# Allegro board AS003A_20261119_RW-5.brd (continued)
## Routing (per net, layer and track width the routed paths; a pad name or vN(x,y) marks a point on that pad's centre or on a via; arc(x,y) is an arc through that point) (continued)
D12705: length 380.6
  L30_DIG w0.081: D127.05 24.12,57.14 24.12,116.27 30.59,122.74 88.68,122.74 100.01,134.07 100.01,152.73 176.13,228.85 219.88,228.85 220.74,229.71 223.68,229.71 224.53,228.85 226.75,228.85 231.7,223.9 264.39,223.9 264.77,223.52 266.83,223.52 269.25,221.11 269.9,221.11 272.28,218.73 272.28,218.02 273.04,217.27 275.63,217.27 275.87,217.03 277.75,217.03
  L30_DIG w0.102: v1(280.03,216.63) 279.63,217.03 277.75,217.03
D12706: length 365.7
  L09_DIG w0.081: 277.75,218.63 276.18,218.63 275.23,219.58 267.26,219.58 262.65,224.18 226.57,224.18 225.45,225.31 152.57,225.31 81.84,154.58 81.84,137.08 73.78,129.02 50.71,129.02 26.67,104.99 26.67,59.86 25.41,58.6
  L09_DIG w0.102: v1(282.43,218.23) 282.03,218.63 277.75,218.63
D12707: length 369.9
  L30_DIG w0.081: D127.07 29.44,57.38 29.44,112.84 34.28,117.68 90.49,117.68 109.52,136.71 109.52,154.42 180.48,225.38 224.99,225.38 228.57,221.8 250.52,221.8 251.24,221.07 266.47,221.07 270.59,216.95 270.59,216.19 271.35,215.43 277.75,215.43
  L30_DIG w0.102: 277.75,215.43 279.63,215.43 v1(280.03,215.03)
D12708: length 353
  L09_DIG w0.081: 277.75,215.43 273.93,215.43 271.87,217.49 261.71,217.49 259.12,220.08 250.03,220.08 249.28,220.83 163.9,220.83 88.76,145.69 88.76,137.54 76.43,125.21 51.83,125.21 31.62,104.99 31.62,59.53 30.53,58.44
  L09_DIG w0.102: v1(282.43,215.03) 282.03,215.43 277.75,215.43
D12709: length 362.2
  L30_DIG w0.081: D127.09 34.18,57.04 34.18,107.53 38.88,112.23 95.08,112.23 119.89,137.03 119.89,159.67 181.06,220.85 224.59,220.85 227.18,218.25 255.15,218.25 256.29,219.39 259.07,219.39 259.38,219.08 265,219.08 270.24,213.83 277.75,213.83
  L30_DIG w0.102: 277.75,213.83 279.63,213.83 v1(280.03,213.43)
D12710: length 344.9
  L09_DIG w0.081: 35.59,58.33 36.82,59.56 36.82,104.04 53.88,121.1 77.63,121.1 93.41,136.88 93.41,145.52 164.15,216.26 250.03,216.26 252.35,213.94 270.29,213.94 270.58,213.65 275.48,213.65 276.1,213.03 277.75,213.03
  L09_DIG w0.102: v1(282.43,212.63) 282.03,213.03 277.75,213.03
D12711: length 383.2
  L32_DIG w0.081: D127.11 39.32,57.1 39.32,118.14 57.8,136.61 113.15,136.61 124.74,148.2 124.74,208.06 138.17,221.49 162.58,221.49 165.65,218.42 247.93,218.42 250.92,215.43 277.75,215.43
  L32_DIG w0.102: v1(279.23,215.03) 278.83,215.43 277.75,215.43
D12712: length 335.2
  L09_DIG w0.081: 40.63,58.09 42.13,59.59 42.13,103.29 56.04,117.2 78.7,117.2 98.62,137.12 98.62,146.34 160.89,208.61 219.85,208.61 220.58,209.34 223.92,209.34 226.43,211.85 275.58,211.85 275.99,211.43 277.75,211.43
  L09_DIG w0.102: v1(280.83,211.03) 280.43,211.43 277.75,211.43
D12713: length 366.5
  L32_DIG w0.081: 277.75,213.03 276.27,213.03 275.52,212.28 225.38,212.28 224.24,213.43 183.57,213.43 180.61,210.46 148.09,210.46 131.86,194.24 131.86,142.97 120.28,131.38 60.28,131.38 44.26,115.36 44.26,56.96 D127.13
  L32_DIG w0.102: v1(279.23,212.63) 278.83,213.03 277.75,213.03
D12714: length 329.1
  L09_DIG w0.081: 277.75,209.83 276.95,209.83 276.07,208.95 267.01,208.95 264.8,206.73 225.8,206.73 223.94,204.87 162.43,204.87 103.92,146.36 103.92,137.3 78.32,111.69 55,111.69 47.06,103.75 47.06,59.76 D127.14
  L09_DIG w0.102: v1(280.83,209.43) 280.43,209.83 277.75,209.83
D12715: length 359
  L32_DIG w0.081: 277.75,209.83 276.39,209.83 275.28,208.72 267.3,208.72 265.34,206.76 149.33,206.76 136.09,193.52 136.09,140.62 121.64,126.17 62.05,126.17 49.61,113.73 49.61,57.23 D127.15
  L32_DIG w0.102: v1(279.23,209.43) 278.83,209.83 277.75,209.83
D12716: length 309.5
  L09_DIG w0.081: D127.16 55.51,63.13 55.51,82.93 107.04,134.47 107.04,144.19 163.51,200.65 250.83,200.65 252.39,202.2 264.59,202.2 269.32,206.93 276.08,206.93 277.38,208.23 277.75,208.23
  L09_DIG w0.102: v1(280.83,207.83) 280.43,208.23 277.75,208.23
D12801: length 473.7
  L32_DIG w0.081: 277.75,223.43 276.62,223.43 275.49,224.56 273.34,224.56 271.44,226.47 256.23,226.47 252.35,230.36 230.99,230.36 227.1,234.24 220.61,234.24 219.86,233.49 10.94,233.49 8.74,231.29 8.74,39.52 D128.01
  L32_DIG w0.102: 277.75,223.43 278.83,223.43 v1(279.23,223.03)
D12802: length 414.8
  L30_DIG w0.081: D128.02 16.57,39.43 16.57,115.5 29.39,128.32 77.07,128.32 85.82,137.07 85.82,160.01 162.63,236.82 226.49,236.82 234.91,228.39 269.41,228.39 272.06,225.74 272.06,224.15 273.99,222.22 273.99,220.16 274.52,219.64 275.81,219.64 276.4,220.23 277.75,220.23
  L30_DIG w0.102: v1(280.03,219.83) 279.63,220.23 277.75,220.23
D12803: length 433.8
  L32_DIG w0.081: D128.03 19.01,36.79 19.01,122.11 44.44,147.54 100.2,147.54 111.04,158.38 111.04,215.71 125.83,230.51 220,230.51 220.6,229.91 223.66,229.91 224.19,230.44 225.37,230.44 228.23,227.58 250.08,227.58 254.82,222.84 266.65,222.84 268.5,220.98 275.3,220.98 276.05,220.23 277.75,220.23
  L32_DIG w0.102: v1(282.43,219.83) 282.03,220.23 277.75,220.23
D12804: length 402.4
  L30_DIG w0.081: D128.04 21.42,39.2 21.42,116.74 30.08,125.4 84.75,125.4 95.87,136.52 95.87,152.77 175.37,232.28 225.57,232.28 231.58,226.27 249.63,226.27 250.68,225.22 267.09,225.22 271.16,221.15 271.79,221.15 272.61,220.33 272.61,218.27 273.05,217.83 277.75,217.83
  L30_DIG w0.102: v1(280.03,217.43) 279.63,217.83 277.75,217.83
D12805: length 423.6
  L32_DIG w0.081: D128.05 24.12,36.82 24.12,123.35 46.24,145.48 102.96,145.48 114.01,156.52 114.01,213.65 127.95,227.59 224.28,227.59 225.4,226.47 249.33,226.47 254.51,221.29 265.72,221.29 267.58,219.43 277.75,219.43
  L32_DIG w0.102: 277.75,219.43 278.83,219.43 v1(279.23,219.03)
D12806: length 394.9
  L30_DIG w0.081: 277.75,216.23 276.95,216.23 276.71,215.99 271.54,215.99 271.07,216.45 271.07,218.2 266.29,222.98 229.42,222.98 224.79,227.62 177.94,227.62 105.17,154.85 105.17,135.33 90.04,120.2 31.96,120.2 26.85,115.09 26.85,39.55 D128.06
  L30_DIG w0.102: 277.75,216.23 279.63,216.23 v1(280.03,215.83)
D12807: length 415.2
  L32_DIG w0.081: D128.07 29.23,36.85 29.23,118.17 53.3,142.24 105.38,142.24 117.24,154.1 117.24,211.5 132.04,226.29 165.92,226.29 169.22,222.99 249.6,222.99 252.09,220.5 261.12,220.5 263.79,217.83 277.75,217.83
  L32_DIG w0.102: 277.75,217.83 278.83,217.83 v1(279.23,217.43)
D12808: length 385
  L30_DIG w0.081: 277.75,214.63 276.31,214.63 276,214.32 271.34,214.32 267.28,218.38 267.28,218.87 265.88,220.27 250.55,220.27 250.16,220.66 226.81,220.66 224.41,223.06 180.46,223.06 115.28,157.89 115.28,134.85 95.29,114.85 36.94,114.85 31.82,109.74 31.82,39.44 D128.08
  L30_DIG w0.102: 277.75,214.63 279.63,214.63 v1(280.03,214.23)
D12809: length 413.8
  L32_DIG w0.081: D128.09 34.28,36.82 34.28,117.68 56.25,139.65 111.2,139.65 121.83,150.28 121.83,210.62 135.19,223.98 165.12,223.98 167.98,221.12 248.73,221.12 252.45,217.4 262.44,217.4 263.89,215.95 276.38,215.95 276.66,216.23 277.75,216.23
  L32_DIG w0.102: 277.75,216.23 282.03,216.23 v1(282.43,215.83)
D12810: length 376
  L30_DIG w0.081: 277.75,213.03 276.16,213.03 275.56,212.43 269.77,212.43 264.89,217.32 225.05,217.32 224.11,218.25 181.16,218.25 124.77,161.86 124.77,135.14 100.01,110.39 42.22,110.39 36.84,105 36.84,39.38 D128.10
  L30_DIG w0.102: 277.75,213.03 279.63,213.03 v1(280.03,212.63)
D12811: length 473.7
  L30_DIG w0.081: 277.75,221.83 276.62,221.83 275.7,222.75 275.7,224.03 273.56,226.17 273.56,227.58 270.47,230.68 267.4,230.68 265.59,232.49 238.92,232.49 238.71,232.7 238.71,233 238.92,233.21 249.51,233.21 249.7,233.4 249.7,233.69 249.47,233.92 234.85,233.92 227.44,241.33 161.88,241.33 81.59,161.04 81.59,149.87 65.7,133.98 28.27,133.98 11.01,116.72 11.01,32.44 13.13,30.33 32.87,30.33 D128.11
  L30_DIG w0.102: 277.75,221.83 279.63,221.83 v1(280.03,221.43)
D12812: length 395.1
  L32_DIG w0.081: D128.12 42.01,39.47 42.01,117.53 58.51,134.02 115.57,134.02 129.55,148 129.55,202.74 146.86,220.06 160.63,220.06 164.66,216.04 248.68,216.04 251.27,213.44 260.85,213.44 261.45,214.04 275.49,214.04 276.08,214.63 277.75,214.63
  L32_DIG w0.102: 277.75,214.63 278.83,214.63 v1(279.23,214.23)
D12813: length 473.7
  L30_DIG w0.081: D128.13 34.67,27.05 11.9,27.05 8.83,30.11 8.83,118.67 27.17,137.01 64.39,137.01 79.39,152.01 79.39,162.98 160.03,243.63 227.66,243.63 229.91,241.38 271.84,241.38 276.4,236.82 276.4,223.58 277.35,222.63 277.75,222.63
  L30_DIG w0.102: 277.75,222.63 279.63,222.63 v1(280.03,223.03)
D12814: length 380.9
  L32_DIG w0.081: D128.14 46.9,39.28 46.9,114.47 61.83,129.4 121.62,129.4 133.76,141.53 133.76,193.69 148.07,208 181.27,208 184.71,211.44 224.87,211.44 225.93,210.39 275.74,210.39 276.79,211.43 277.75,211.43
  L32_DIG w0.102: v1(279.23,211.03) 278.83,211.43 277.75,211.43
D12815: length 456.5
  L07_DIG w0.081: D128.15 62.85,20.97 269.27,20.97 290.03,41.74 313.91,41.74 316.37,44.2 316.37,121.01 300.08,137.3 300.08,164.09 300.9,164.92 300.9,170.65 300.03,171.53 300.03,175.28 301.04,176.3 301.04,189.11 296.79,193.36 296.79,199.92 296.43,200.27 296.43,201.55
  L07_DIG w0.102: 296.43,201.55 296.43,205.73 296.33,205.83 295.63,205.83 v1(295.23,206.23)
D12816: length 327.7
  L09_DIG w0.081: 277.75,206.63 277.11,206.63 275.58,205.1 269.22,205.1 261.55,197.43 226.28,197.43 224.49,195.64 161.01,195.64 109.32,143.95 109.32,132.36 58.39,81.43 58.39,45.69 D128.16
  L09_DIG w0.102: 277.75,206.63 280.43,206.63 v1(280.83,206.23)
D12901: length 433.8
  L07_DIG w0.081: D129.01 84.56,94.72 84.56,45.19 80.77,41.39 67.61,41.39 63.22,45.78 63.22,60.16 69,65.95 77.85,65.95 79.16,67.26 79.16,148.81 139.42,209.07 151.88,209.07 174.91,232.1 224.24,232.1 227.88,228.46 249.89,228.46 251.96,226.38 267.51,226.38 268.92,224.97 268.92,223.59 269.71,222.81 275.71,222.81 276.68,221.83 277.75,221.83
  L07_DIG w0.102: 277.75,221.83 281.23,221.83 v1(281.63,221.43)
D12902: length 314.6
  L03_DIG w0.096: 277.75,208.63 277.67,208.63 277.59,208.63 277.57,208.61 277.3,208.6 276.19,208.6 275.92,208.87 269.95,208.87 266.58,212.25 229.34,212.25 227.57,214.02 177.03,214.02 84.47,121.46 84.47,109.58 76.29,101.4 76.29,84.1 78.49,81.9 83.55,81.9 85.04,83.39 85.04,100.85 87.01,102.83 90.33,102.83 91.25,101.91 91.25,100.82 90.68,100.25 90.09,100.25 D129.02
  L03_DIG w0.102: 277.75,208.63 v1(278.43,208.63)
D12903: length 279.8
  L07_DIG w0.081: 277.75,219.43 271.67,219.43 270.05,221.05 269.49,221.05 267.87,222.67 267.87,224.27 266.68,225.46 251.52,225.46 249.73,227.25 226.36,227.25 223.78,229.83 220.74,229.83 219.72,228.81 174.24,228.81 94.33,148.9 94.33,107.36 92.41,105.44 92.41,97.49 D129.03
  L07_DIG w0.102: v1(281.63,219.03) 281.23,219.43 277.75,219.43
D12904: length 314.6
  L03_DIG w0.096: D129.04 91.62,101.42 91.62,102.06 90.48,103.2 86.86,103.2 84.67,101.01 84.67,83.54 83.4,82.27 78.64,82.27 76.66,84.25 76.66,101.25 84.83,109.42 84.83,121.3 177.19,213.65 227.41,213.65 229.19,211.88 266.42,211.88 269.8,208.51 275.76,208.51 276.03,208.24 277.31,208.24 277.58,208.24 277.6,208.23 277.68,208.23 277.75,208.23
  L03_DIG w0.102: 277.75,208.23 278.83,208.23 v1(279.23,208.63)
D12905: length 275.6
  L07_DIG w0.081: 277.75,217.83 271.42,217.83 266.28,222.97 252.47,222.97 249.22,226.23 225.9,226.23 224.58,227.54 175.48,227.54 100.48,152.54 100.48,111.04 97.83,108.38 97.83,97.83 D129.05
  L07_DIG w0.102: 277.75,217.83 281.93,217.83 282.03,217.93 282.03,218.63 v1(282.43,219.03)
D12906: length 314.6
  L03_DIG w0.096: D129.06 100.41,100.41 100.41,103.2 98.81,104.8 86.18,104.8 83.6,102.22 83.6,87.31 82.39,86.11 79.33,86.11 77.92,87.52 77.92,100.88 86.11,109.07 86.11,120.76 177.12,211.77 226.1,211.77 227.57,210.3 265,210.3 268.24,207.06 275.82,207.06 276.17,207.41 277.59,207.41 277.61,207.43 277.75,207.43
  L03_DIG w0.102: v1(279.23,207.03) 278.83,207.43 277.75,207.43
D12907: length 269
  L07_DIG w0.081: 277.75,216.23 276.54,216.23 275.38,217.39 270.11,217.39 266.44,221.06 251.99,221.06 249.15,223.9 226.48,223.9 225.12,225.27 176.15,225.27 105.87,154.98 105.87,108.63 102.83,105.59 102.83,97.75 D129.07
  L07_DIG w0.102: 277.75,216.23 281.23,216.23 v1(281.63,215.83)
D12908: length 314.6
  L03_DIG w0.096: D129.08 103.24,99.96 101.96,99.96 100.78,101.13 100.78,103.35 98.96,105.17 86.02,105.17 83.23,102.38 83.23,87.47 82.24,86.48 79.48,86.48 78.29,87.67 78.29,100.72 86.48,108.92 86.48,120.61 177.28,211.4 225.95,211.4 227.42,209.93 264.84,209.93 268.08,206.69 275.97,206.69 276.33,207.05 277.59,207.05 277.61,207.03 277.75,207.03
  L03_DIG w0.102: 277.75,207.03 v1(278.43,207.03)
D12909: length 265.6
  L07_DIG w0.081: 277.75,214.63 276.5,214.63 275.65,215.49 270.5,215.49 267.69,218.3 267.69,218.64 266.09,220.23 251.55,220.23 248.79,222.99 175.8,222.99 110.99,158.18 110.99,107.83 108.01,104.85 108.01,97.85 D129.09
  L07_DIG w0.102: v1(282.43,214.23) 282.03,214.63 277.75,214.63
D12910: length 239.2
  L03_DIG w0.096: 277.25,205.62 276.1,205.62 275.72,205.24 269.13,205.24 267.49,203.61 229.57,203.61 228,202.04 169.94,202.04 111.4,143.51 111.4,101.24 D129.10
  L03_DIG w0.102: v1(279.23,205.43) 278.83,205.83 277.75,205.83 277.54,205.62 277.25,205.62
D12911: length 259.9
  L07_DIG w0.081: D129.11 112.86,97.62 112.86,104.03 116.55,107.73 116.55,160.59 176.73,220.76 249.5,220.76 252.82,217.45 266.79,217.45 270.05,214.19 275.91,214.19 276.27,213.83 277.75,213.83
  L07_DIG w0.102: v1(282.43,213.43) 282.03,213.83 277.75,213.83
D12912: length 239.2
  L03_DIG w0.096: D129.12 112.95,100.41 112.16,100.41 111.77,100.8 111.77,143.35 170.09,201.67 228.16,201.67 229.72,203.24 267.65,203.24 269.28,204.88 275.88,204.88 276.25,205.25 277.25,205.25
  L03_DIG w0.102: 277.25,205.25 277.26,205.24 277.54,205.24 277.75,205.03 278.83,205.03 v1(279.23,204.63)
D12913: length 254.2
  L07_DIG w0.081: D129.13 118.21,97.89 118.21,106.51 120.69,108.99 120.69,162.79 176.32,218.42 247.82,218.42 249.85,216.39 263.38,216.39 263.98,215.79 267.29,215.79 269.38,213.7 275.43,213.7 276.1,213.03 277.75,213.03
  L07_DIG w0.102: 277.75,213.03 281.23,213.03 v1(281.63,212.63)
D12914: length 239.2
  L03_DIG w0.096: 277.38,202.42 276.51,202.42 276.02,201.93 272.79,201.93 272.39,202.34 259.74,202.34 258.09,200.68 176.53,200.68 170.24,194.38 170.24,181.94 160.18,171.88 143.37,171.88 121.36,149.87 121.36,101.04 D129.14
  L03_DIG w0.102: 277.38,202.42 277.67,202.42 277.88,202.63 278.83,202.63 v1(279.23,203.03)
D12915: length 249.2
  L07_DIG w0.081: D129.15 123.19,97.79 123.19,104.74 124.42,105.97 124.42,164.1 176.53,216.2 224.37,216.2 225.3,215.27 248.91,215.27 250.7,213.48 268.46,213.48 269.7,212.23 277.75,212.23
  L07_DIG w0.102: 277.75,212.23 281.23,212.23 v1(281.63,211.83)
D12916: length 239.2
  L03_DIG w0.096: 277.38,202.05 276.67,202.05 276.18,201.56 272.64,201.56 272.23,201.97 259.89,201.97 258.24,200.32 176.69,200.32 170.6,194.23 170.6,181.78 160.33,171.51 143.52,171.51 121.73,149.72 121.73,101.27 122.67,100.33 123.19,100.33 D129.16
  L03_DIG w0.102: 277.38,202.05 277.39,202.04 277.67,202.04 277.88,201.83 278.83,201.83 v1(279.23,202.23)
D13001: length 327.7
  L09_DIG w0.081: 281.23,201.55 281.23,201.29 280.74,200.8 276.75,200.8 275.08,199.13 268.16,199.13 257.04,188.01 224.64,188.01 223.94,188.71 220.63,188.71 219.88,187.96 195.24,187.96 188.5,181.23 149.88,181.23 114.45,145.79 114.45,132.55 75,93.11 75,57.13 76.49,55.64 80.11,55.64 81.7,57.24 81.7,71.54 D130.01
  L09_DIG w0.102: 281.23,201.55 281.23,204.23 v1(281.63,204.63)
D13002: length 273.7
  L09_DIG w0.081: 282.03,201.55 282.03,200.82 280.95,199.73 277.32,199.73 275.95,198.37 275.95,196.41 274.62,195.08 274.62,190.68 270.99,187.05 224.69,187.05 224.06,186.42 199.63,186.42 187.48,174.27 146.41,174.27 115.66,143.52 115.66,130.87 90.25,105.46 90.25,80.09 D130.02
  L09_DIG w0.102: 282.03,201.55 282.03,204.23 v1(282.43,204.63)
D13003: length 276.9
  L09_DIG w0.081: D130.03 92.61,77.37 92.61,104.34 119.22,130.95 119.22,141.67 150.19,172.64 191.13,172.64 201.78,183.29 219.96,183.29 220.88,184.21 223.78,184.21 225.22,185.65 273.79,185.65 275.51,187.38 275.51,194.28 277.71,196.48 282.21,196.48 282.51,196.78 282.51,199.17 283.11,199.77 284.22,199.77 285.23,200.78 285.23,201.55
  L09_DIG w0.102: 285.23,201.55 285.23,204.23 v1(285.63,204.63)
D13004: length 271.2
  L09_DIG w0.081: D130.04 95.61,80.37 95.61,103.69 120.74,128.82 120.74,138.17 154.07,171.51 194.41,171.51 204.76,181.85 224.67,181.85 225.11,182.3 270.41,182.3 272.8,184.68 276.53,184.68 277.69,185.84 277.69,191.14 279.49,192.95 281.3,192.95 282.99,194.63 283.84,194.63 284.7,195.5 284.7,199.29 286.03,200.62 286.03,201.55
  L09_DIG w0.102: 286.03,201.55 286.03,204.23 v1(286.43,204.63)
D13005: length 265.4
  L09_DIG w0.081: 286.83,201.55 286.83,200.5 285.83,199.5 285.83,195.26 283.77,193.2 282.88,193.2 280.68,191 280.68,189.53 278.79,187.64 278.79,185.09 274.1,180.4 227.64,180.4 224.5,177.27 204.31,177.27 172.33,145.29 140.96,145.29 97.89,102.22 97.89,77.57 D130.05
  L09_DIG w0.102: v1(287.23,204.63) 286.83,204.23 286.83,201.55
D13006: length 515.3
  L34_DIG w0.102: 280.03,227.71 v1(280.03,227.03)
  L34_DIG w0.104: D130.06 87.27,90.53 14.12,90.53 11.36,93.29 11.36,195.5 72.22,256.36 273.38,256.36 277.95,251.78 277.95,243.11 280.03,241.04 280.03,227.71
GPDPS1_1F:
  vias: v1(221.62,171.58) v1(221.62,169.29) v1(221.62,167) v1(221.62,164.72)
GPDPS1_1GS:
  vias: v1(221.62,185.29)
GPDPS1_1S:
  vias: v1(221.62,183.01)
GPDPS1_2F:
  vias: v1(323.47,163.01)
GPDPS1_2GS:
  vias: v1(325.75,163.01)
GPDPS1_2S:
  vias: v1(321.18,163.01)
GPDPS1_3F:
  vias: v1(361.82,163.01)
GPDPS1_3GS:
  vias: v1(366.39,163.01)
GPDPS1_3S:
  vias: v1(364.11,163.01)
GPDPS1_4F:
  vias: v1(340.87,163.01)
GPDPS1_4GS:
  vias: v1(345.44,163.01)
GPDPS1_4S:
  vias: v1(343.15,163.01)
GPDPS2_1F:
  vias: v1(398.97,230.76) v1(398.97,230) v1(398.97,228.47) v1(398.97,227.71)
GPDPS2_1GS:
  vias: v1(398.97,233.04) v1(398.97,232.28)
GPDPS2_1S:
  vias: v1(398.97,235.33) v1(398.97,234.57)
GPDPS2_2F:
  vias: v1(398.97,250.32) v1(398.97,249.56)
GPDPS2_2GS:
  vias: v1(398.97,252.6) v1(398.97,251.84)
GPDPS2_2S:
  vias: v1(398.97,254.89) v1(398.97,254.13)
GPDPS2_3F:
  vias: v1(380.04,211.71) v1(380.04,200.03) v1(380.04,183.51) v1(380.04,170.05)
GPDPS2_3GS:
  vias: v1(380.04,214) v1(380.04,188.09) v1(380.04,172.34)
GPDPS2_3S:
  vias: v1(380.04,185.8)
GPDPS2_4F:
  vias: v1(380.37,239.01) v1(380.37,236.73) v1(380.37,234.44) v1(380.37,232.16)
GPDPS2_4GS:
  vias: v1(380.37,243.59)
GPDPS2_4S:
  vias: v1(380.37,241.3)
GPDPS3_1F:
  vias: v1(221.49,215.01) v1(221.49,212.72) v1(221.49,210.44) v1(221.49,208.15)
GPDPS3_1GS:
  vias: v1(221.49,228.73)
GPDPS3_1S:
  vias: v1(221.49,226.44)
GPDPS3_2F:
  vias: v1(251.33,147.64) v1(253.62,147.64) v1(266.83,147.64)
GPDPS3_2GS:
  vias: v1(273.69,147.64)
GPDPS3_2S:
  vias: v1(271.4,147.64)
GPDPS3_3F:
  vias: v1(286.89,147.64) v1(320.42,147.64)
GPDPS3_3GS:
  vias: v1(291.46,147.64)
GPDPS3_3S:
  vias: v1(289.18,147.64)
GPDPS3_4F:
  vias: v1(303.4,147.64)
GPDPS3_4GS:
  vias: v1(307.97,147.64)
GPDPS3_4S:
  vias: v1(305.69,147.64)
S1_CBIT001:
  vias: v1(321.94,226.33)
S1_CBIT002:
  vias: v1(321.94,243.6)
S1_CBIT003: length 2.6
  TOP w0.508: DV4.2 292.35,249.4 K3.8
S1_CBIT004: length 2.6
  TOP w0.508: K4.8 281.31,249.4 DV5.2
S1_CBIT005: length 2.6
  TOP w0.508: DV6.2 256.06,204.98 K5.8
S1_CBIT006: length 2.6
  TOP w0.508: K6.8 328.52,217.68 DV7.2
S1_CBIT007: length 2.6
  TOP w0.508: DV8.2 299.72,180.12 K7.8
S1_CBIT008: length 2.6
  TOP w0.508: DV9.2 328.52,200.41 K8.8
S1_CBIT009: length 2.6
  TOP w0.508: DV10.2 287.53,180.12 K9.8
S1_CBIT010: length 2.6
  TOP w0.508: DV11.2 352.65,230.63 K10.8
S1_CBIT011: length 2.6
  TOP w0.508: DV12.2 352.65,247.9 K11.8
S1_CBIT012: length 2.6
  TOP w0.508: DV13.2 369.92,242.32 K12.8
S1_CSDPS001F:
  vias: v1(359.54,163.01)
S1_CSDPS001GS:
  vias: v1(354.96,163.01)
S1_CSDPS001S:
  vias: v1(357.25,163.01)
S1_CSDPS002F:
  vias: v1(338.58,163.01)
S1_CSDPS002GS:
  vias: v1(334.01,163.01)
S1_CSDPS002S:
  vias: v1(336.3,163.01)
S1_CSDPS003-1F:
  vias: v1(398.97,226.19) v1(398.97,225.42) v1(398.97,223.9) v1(398.97,223.14)
S1_CSDPS003-1GS:
  vias: v1(398.97,221.62) v1(398.97,220.85)
S1_CSDPS003-1S:
  vias: v1(398.97,219.33) v1(398.97,218.57)
S1_CSDPS004-1F:
  vias: v1(398.97,248.03) v1(398.97,247.27)
S1_CSDPS004-1GS:
  vias: v1(398.97,245.75) v1(398.97,244.98)
S1_CSDPS004-1S:
  vias: v1(398.97,243.46) v1(398.97,242.7)
S1_CSDPS005-1F:
  vias: v1(262.25,147.64) v1(264.54,147.64)
S1_CSDPS005-1GS:
  vias: v1(257.68,147.64) v1(259.97,147.64)
S1_CSDPS006-1F:
  vias: v1(246.76,147.64) v1(249.05,147.64)
S1_CSDPS006-1GS:
  vias: v1(242.19,147.64)
S1_CSDPS006-1S:
  vias: v1(244.47,147.64)
S1_CSDPS007-1F:
  vias: v1(282.32,147.64)
S1_CSDPS007-1GS:
  vias: v1(280.03,147.64)
S1_CSDPS007-1S:
  vias: v1(284.61,147.64)
S1_CSDPS008-1F:
  vias: v1(315.85,147.64)
S1_CSDPS008-1GS:
  vias: v1(313.56,147.64)
S1_CSDPS008-1S:
  vias: v1(318.13,147.64)
S1_CSDPS009F:
  vias: v1(380.04,195.45)
S1_CSDPS009GS:
  vias: v1(380.04,193.17)
S1_CSDPS009S:
  vias: v1(380.04,197.74)
S1_CSDPS010-1F:
  vias: v1(301.12,147.64)
S1_CSDPS010-1GS:
  vias: v1(296.54,147.64)
S1_CSDPS010-1S:
  vias: v1(298.83,147.64)
S1_CSDPS011F:
  vias: v1(380.04,178.94)
S1_CSDPS011GS:
  vias: v1(380.04,176.66)
S1_CSDPS011S:
  vias: v1(380.04,181.23)
S1_CSDPS012F:
  vias: v1(318.9,163.01)
S1_CSDPS012GS:
  vias: v1(314.32,163.01)
S1_CSDPS012S:
  vias: v1(316.61,163.01)
S1_CSDPS013-1F:
  vias: v1(221.49,224.16) v1(221.49,221.87) v1(221.49,219.58) v1(221.49,217.3)
S1_CSDPS013-1GS:
  vias: v1(221.49,203.58)
S1_CSDPS013-1S:
  vias: v1(221.49,205.87)
S1_CSDPS014-1F:
  vias: v1(380.37,229.87) v1(380.37,227.58) v1(380.37,225.3) v1(380.37,223.01)
S1_CSDPS014-1GS:
  vias: v1(221.62,160.15) v1(380.37,218.44)
S1_CSDPS014-1S:
  vias: v1(380.37,220.73)
S1_CSDPS015-1F:
  vias: v1(221.62,180.72) v1(221.62,178.44) v1(221.62,176.15) v1(221.62,173.86)
S1_CSDPS015-1S:
  vias: v1(221.62,162.43)
S1_CSDPS016F:
  vias: v1(380.04,209.42)
S1_CSDPS016GS:
  vias: v1(380.04,204.85)
S1_CSDPS016S:
  vias: v1(380.04,207.14)
S1_CSDPS017F:
  vias: v1(380.04,167.77)
S1_CSDPS017S:
  vias: v1(380.04,165.48)
S1_D5C0_ZQPAD: length 1.6
  BOTTOM w0.508: R112.1 R113.1
  vias: v1(281.63,209.43)
S1_D5C0_ZQPAD_A: length 3
  BOTTOM w0.508: R113.2 K5.3
S1_D5C1_ZQPAD: length 1.6
  BOTTOM w0.508: R114.1 R115.1
  vias: v1(299.23,218.23)
S1_D5C1_ZQPAD_A: length 3
  BOTTOM w0.508: R115.2 K6.3
S1_DPS1: length 10.2
  BOTTOM w0.508: v1(298.83,149.54) v1(298.83,150.81) v1(298.83,152.08) ; v1(301.12,152.08) v1(301.12,150.81) v1(301.12,149.54) ; v1(303.4,152.08) v1(303.4,150.81) v1(303.4,149.54) ; v1(305.69,152.08) v1(305.69,150.81) v1(305.69,149.54)
  vias: v1(287.23,215.03) v1(295.23,215.03) v1(299.08,173.86) v1(299.97,169.54) v1(300.99,174.2) v1(302.89,174.3) v1(303.53,169.5)
S1_DPS3: length 10.2
  BOTTOM w0.508: v1(378.15,178.94) v1(376.88,178.94) v1(375.61,178.94) ; v1(375.61,183.51) v1(376.88,183.51) v1(378.15,183.51) ; v1(375.61,185.8) v1(376.88,185.8) v1(378.15,185.8) ; v1(375.61,181.23) v1(376.88,181.23) v1(378.15,181.23)
  vias: v1(292.83,207.83) v1(303.28,199.13) v1(303.28,195.67) v1(303.28,191.96) v1(303.28,187.43) v1(303.28,182.12)
S1_DPS4: length 10.2
  BOTTOM w0.508: v1(316.61,164.91) v1(316.61,166.18) v1(316.61,167.45) ; v1(318.9,164.91) v1(318.9,166.18) v1(318.9,167.45) ; v1(321.18,167.45) v1(321.18,166.18) v1(321.18,164.91) ; v1(323.47,167.45) v1(323.47,166.18) v1(323.47,164.91)
  vias: v1(272.54,186.69) v1(276.61,191.45) v1(276.61,186.67) v1(278.13,199.13) v1(278.13,195.67) v1(290.43,213.43)
S1_DPS5: length 10.2
  BOTTOM w0.508: v1(284.61,152.08) v1(284.61,150.81) v1(284.61,149.54) ; v1(282.32,152.08) v1(282.32,150.81) v1(282.32,149.54) ; v1(289.18,152.08) v1(289.18,150.81) v1(289.18,149.54) ; v1(286.89,152.08) v1(286.89,150.81) v1(286.89,149.54)
  vias: v1(266.06,169.16) v1(270.51,169.52) v1(274.32,169.22) v1(276.86,169.12) v1(278.76,168.78) v1(286.43,217.43) v1(286.43,215.83) v1(286.43,214.23) v1(286.43,212.63) v1(286.43,211.03) v1(286.43,209.43) v1(287.23,216.63) v1(287.23,213.43) v1(287.23,211.83) v1(287.23,210.23) v1(287.23,208.63) v1(288.03,215.83)
S1_DPS7: length 7.6
  BOTTOM w0.508: v1(315.85,152.08) v1(315.85,150.81) v1(315.85,149.54) ; v1(320.42,149.54) v1(320.42,150.81) v1(320.42,152.08) ; v1(318.13,152.08) v1(318.13,150.81) v1(318.13,149.54)
  vias: v1(294.43,217.43) v1(294.43,215.83) v1(294.43,214.23) v1(294.43,212.63) v1(294.43,211.03) v1(294.43,209.43) v1(295.23,216.63) v1(295.23,213.43) v1(295.23,211.83) v1(295.23,210.23) v1(295.23,208.63) v1(305.82,198.87) v1(305.82,195.67) v1(305.82,191.96) v1(305.82,187.43) v1(309.63,187.45)
S1_DPS9: length 10.2
  BOTTOM w0.508: v1(359.54,164.91) v1(359.54,166.18) v1(359.54,167.45) ; v1(361.82,167.45) v1(361.82,166.18) v1(361.82,164.91) ; v1(364.11,164.91) v1(364.11,166.18) v1(364.11,167.45) ; v1(357.25,164.91) v1(357.25,166.18) v1(357.25,167.45)
  vias: v1(291.23,214.23) v1(306.33,201.93) v1(309.79,201.93) v1(320.67,184.91) v1(320.74,191.52) v1(320.7,188.72)
S1_DPS10: length 10.2
  BOTTOM w0.508: v1(338.58,167.45) v1(338.58,166.18) v1(338.58,164.91) ; v1(343.15,164.91) v1(343.15,166.18) v1(343.15,167.45) ; v1(340.87,167.45) v1(340.87,166.18) v1(340.87,164.91) ; v1(336.3,164.91) v1(336.3,166.18) v1(336.3,167.45)
  vias: v1(263.12,200.91) v1(263.14,196.6) v1(267.65,200.91) v1(271.61,200.91) v1(274.33,200.91) v1(288.03,207.83) v1(289.63,207.83) v1(291.23,207.83)
S1_DPS11: length 3.8
  BOTTOM w0.508: v1(376.88,207.14) v1(378.15,207.14) ; v1(378.15,211.71) v1(376.88,211.71) ; v1(376.88,209.42) v1(378.15,209.42)
  vias: v1(337.69,249.17) v1(337.75,247.1) v1(337.69,231.9) v1(337.75,229.83) v1(338.78,234.26) v1(339.78,236.81) v1(353.84,235.53) v1(353.84,233.75) v1(354.83,240.83) v1(355.03,242.9) v1(364.36,235.96) v1(366.39,235.8) v1(366.39,230.89) v1(369.19,235.9) v1(372.24,235.95)
S1_DPS12: length 10.7
  BOTTOM w0.254: 292.95,184.32 C418.1 292.95,183.22
  BOTTOM w0.508: v1(375.61,170.05) v1(376.88,170.05) v1(378.15,170.05) ; v1(378.15,167.77) v1(376.88,167.77) v1(375.61,167.77) ; OSC1.4 292.95,184.32 ; v1(292.95,182.48) 292.95,183.22 ; v1(378.15,165.48) v1(376.88,165.48) v1(375.61,165.48)
  vias: v1(285.15,190.45) v1(288.04,175.7) v1(290.83,175.75) v1(291.34,180.94) v1(293.12,180.84) v1(294.39,175.77)
S1_DPS17: length 10
  BOTTOM w0.762: 392.43,225.86 392.48,225.81 BD13.1 ; 392.43,225.86 v1(392.43,224.79) v1(392.43,222.76) ; 392.43,225.86 v1(392.43,226.57) ; v1(391.16,226.57) v1(391.16,224.79) v1(391.16,222.76) v1(391.16,220.73)
  vias: v1(287.23,218.23) v1(288.03,219.03) v1(288.83,218.23) v1(289.63,219.03) v1(289.63,217.43) v1(290.43,218.23) v1(291.23,219.03) v1(291.23,217.43) v1(292.03,218.23) v1(292.83,219.03) v1(293.63,218.23) v1(295.23,218.23) v1(355.97,216.28) v1(356.45,218.44) v1(356.55,220.98) v1(359.16,220.98) v1(359.43,216.53) v1(392.43,220.73) v1(397.07,235.33) v1(397.07,234.57) v1(397.07,219.33) v1(397.07,218.57)
S1_DPS20: length 14.4
  TOP w0.762: S1_DPS20.1 396.49,243.08
  BOTTOM w0.762: 392.43,247.7 v1(392.43,246.63) v1(392.43,244.6) ; 392.43,247.7 392.48,247.65 BD16.1 ; 392.43,247.7 v1(392.43,248.41) v1(392.43,249.94) ; BD15.1 v1(392.43,249.94) ; v1(392.43,249.94) v1(391.16,249.94) v1(391.16,248.41) v1(391.16,246.63) v1(391.16,244.6)
  vias: v1(286.43,220.63) v1(286.43,219.03) v1(287.23,219.83) v1(288.83,219.83) v1(290.43,219.83) v1(292.03,219.83) v1(293.63,219.83) v1(294.43,220.63) v1(294.43,219.03) v1(295.23,219.83) v1(342.13,215.9) v1(342.48,218.44) v1(342.58,220.98) v1(345.82,220.98) v1(346.1,216.53) v1(397.07,254.89) v1(397.07,254.13) v1(397.07,243.46) v1(397.07,242.7)
S1_DPS23: length 10.2
  BOTTOM w0.508: v1(266.83,149.54) v1(266.83,150.81) v1(266.83,152.08) ; v1(264.54,149.54) v1(264.54,150.81) v1(264.54,152.08) ; v1(269.11,149.54) v1(269.11,150.81) v1(269.11,152.08) ; v1(262.25,149.54) v1(262.25,150.81) v1(262.25,152.08)
  vias: v1(259.97,149.54) v1(261.87,231.14) v1(261.85,227.33) v1(266.89,227.33) v1(271.36,227.33) v1(271.4,149.54) v1(275.33,227.33) v1(283.23,222.23) v1(283.23,220.63) v1(283.23,219.03) v1(283.23,217.43) v1(283.23,215.83) v1(283.23,214.23) v1(283.23,212.63) v1(283.23,211.03) v1(283.23,209.43) v1(283.23,207.83)
S1_DPS27: length 13
  BOTTOM w0.152: v1(306.49,228.6) C198.1
  BOTTOM w0.508: v1(253.62,152.08) v1(253.62,150.81) v1(253.62,149.54) ; v1(249.05,152.08) v1(249.05,150.81) v1(249.05,149.54) ; v1(246.76,149.54) v1(246.76,150.81) v1(246.76,152.08) ; v1(251.33,152.08) v1(251.33,150.81) v1(251.33,149.54) ; v1(244.47,149.54) v1(244.47,150.81) v1(244.47,152.08)
  vias: v1(298.43,223.03) v1(298.43,221.43) v1(298.43,219.83) v1(298.43,218.23) v1(298.43,216.63) v1(298.43,215.03) v1(298.43,213.43) v1(298.43,211.83) v1(298.43,210.23) v1(298.43,208.63) v1(298.43,207.03) v1(309.89,228.6) v1(313.29,228.6) v1(317.75,234.95) v1(318.03,231.39)
S1_DPS31: length 10
  BOTTOM w0.508: v1(375.61,197.74) v1(376.88,197.74) v1(378.15,197.74) ; C137.1 320.7,196.99 K8.4 ; v1(375.61,200.03) v1(376.88,200.03) v1(378.15,200.03) ; v1(378.15,195.45) v1(376.88,195.45) v1(375.61,195.45)
  vias: v1(324.49,194.56) v1(327.7,194.56) v1(327.79,191.96) v1(331.09,192) v1(335.41,192.02)
S1_DPS33:
  vias: v1(223.52,196.72) v1(223.52,194.44) v1(223.52,192.15) v1(223.52,189.87) v1(223.52,187.58) v1(223.52,183.01) v1(223.52,180.72) v1(223.52,178.44) v1(223.52,176.15) v1(223.52,173.86) v1(223.52,171.58) v1(223.52,169.29) v1(223.52,167) v1(223.52,164.72) v1(223.52,162.43) v1(248.73,195.45) v1(248.73,189.61) v1(248.73,183.77) v1(248.73,177.93) v1(248.73,172.08) v1(248.73,166.24) v1(265.68,177.04) v1(269.75,176.97) v1(273.05,181.44) v1(273.3,176.97) v1(276.86,181.44) v1(276.86,176.97) v1(279.91,198.97) v1(279.91,195.67) v1(279.91,191.7) v1(279.91,186.67) v1(279.91,181.44) v1(279.91,177.13) v1(281.69,198.97) v1(281.69,195.57) v1(283.46,198.97) v1(283.46,195.67) v1(285.24,198.97) v1(285.24,195.57) v1(287.02,198.97) v1(287.02,195.57) v1(288.03,217.43) v1(288.03,214.23) v1(288.03,212.63) v1(288.03,211.03) v1(288.03,209.43) v1(288.83,216.63) v1(288.83,215.03) v1(288.83,213.43) v1(288.83,211.83) v1(288.83,210.23) v1(288.83,208.63) v1(288.8,198.97) v1(288.8,195.57) v1(289.63,215.83) v1(289.63,214.23) v1(289.63,212.63) v1(289.63,211.03) v1(289.63,209.43) v1(290.43,216.63) v1(290.43,215.03) v1(290.43,211.83) v1(290.43,210.23) v1(290.43,208.63) v1(290.58,198.97) v1(290.58,195.57) v1(291.23,215.83) v1(291.23,212.63) v1(291.23,211.03) v1(291.23,209.43) v1(292.03,216.63) v1(292.03,215.03) v1(292.03,213.43) v1(292.03,211.83) v1(292.03,210.23) v1(292.03,208.63) v1(292.35,198.97) v1(292.35,195.57) v1(292.83,217.43) v1(292.83,215.83) v1(292.83,214.23) v1(292.83,212.63) v1(292.83,211.03) v1(292.83,209.43) v1(293.63,216.63) v1(293.63,215.03) v1(293.63,213.43) v1(293.63,211.83) v1(293.63,210.23) v1(293.63,208.63) v1(294.13,198.97) v1(294.13,195.57) v1(295.91,198.97) v1(295.91,195.57) v1(297.69,198.97) v1(297.69,195.57) v1(299.47,198.97) v1(299.47,195.57) v1(301.24,198.97) v1(301.24,195.57)
S1_DPS49:
  vias: v1(223.39,240.16) v1(223.39,237.87) v1(223.39,235.58) v1(223.39,233.3) v1(223.39,231.01) v1(223.39,226.44) v1(223.39,224.16) v1(223.39,221.87) v1(223.39,219.58) v1(223.39,217.3) v1(223.39,215.01) v1(223.39,212.72) v1(223.39,210.44) v1(223.39,208.15) v1(223.39,205.87) v1(248.67,236.47) v1(248.67,231.14) v1(248.67,225.3) v1(248.67,219.46) v1(248.67,213.61) v1(248.67,208.03) v1(248.67,201.93) v1(258.13,218.44) v1(258.13,214.88) v1(260.03,222) v1(266.43,222) v1(266.53,218.44) v1(266.53,216.66) v1(266.53,214.88) v1(266.79,224.03) v1(271.26,225.55) v1(271.36,223.77) v1(271.46,222) v1(271.77,220.22) v1(271.77,218.44) v1(271.77,216.66) v1(271.77,214.88) v1(271.77,213.11) v1(271.77,211.33) v1(271.77,209.55) v1(271.77,207.77) v1(271.77,205.99) v1(271.77,204.22) v1(275.17,225.55) v1(275.17,223.77) v1(275.17,222) v1(275.17,220.22) v1(275.17,218.44) v1(275.17,216.66) v1(275.17,214.88) v1(275.17,213.11) v1(275.17,211.33) v1(275.17,209.55) v1(275.17,207.77) v1(275.17,205.99) v1(275.17,204.22) v1(275.17,202.44) v1(284.03,221.43) v1(284.03,219.83) v1(284.03,218.23) v1(284.03,216.63) v1(284.03,215.03) v1(284.03,213.43) v1(284.03,211.83) v1(284.03,210.23) v1(284.03,208.63) v1(284.83,222.23) v1(284.83,220.63) v1(284.83,219.03) v1(284.83,217.43) v1(284.83,215.83) v1(284.83,214.23) v1(284.83,212.63) v1(284.83,211.03) v1(284.83,209.43) v1(284.83,207.83) v1(285.63,216.63) v1(285.63,215.03) v1(285.63,213.43) v1(285.63,211.83) v1(285.63,210.23) v1(285.63,208.63) v1(285.63,207.03)
S1_DPS57: length 0.3
  BOTTOM w0.152: C375.1 v1(306.49,226.82)
  vias: v1(296.03,217.43) v1(296.03,215.83) v1(296.03,214.23) v1(296.03,212.63) v1(296.03,211.03) v1(296.03,209.43) v1(296.83,221.43) v1(296.83,219.83) v1(296.83,218.23) v1(296.83,216.63) v1(296.83,215.03) v1(296.83,213.43) v1(296.83,211.83) v1(296.83,210.23) v1(296.83,208.63) v1(296.83,207.03) v1(297.63,222.23) v1(297.63,220.63) v1(297.63,219.03) v1(297.63,217.43) v1(297.63,215.83) v1(297.63,214.23) v1(297.63,212.63) v1(297.63,211.03) v1(297.63,209.43) v1(297.63,207.83) v1(306.49,225.04) v1(306.49,223.27) v1(306.49,221.49) v1(306.49,219.71) v1(306.49,217.93) v1(306.49,216.15) v1(306.49,214.38) v1(306.49,212.6) v1(306.49,210.82) v1(306.49,209.04) v1(306.49,207.26) v1(306.49,205.49) v1(306.49,203.71) v1(309.89,226.82) v1(309.89,225.04) v1(309.89,223.27) v1(309.89,221.49) v1(309.89,219.71) v1(309.89,217.93) v1(309.89,216.15) v1(309.89,214.38) v1(309.89,212.6) v1(309.89,210.82) v1(309.89,209.04) v1(309.89,207.26) v1(309.89,205.49) v1(309.89,203.71) v1(313.35,226.82) v1(313.28,225.04) v1(313.39,223.27) v1(318.06,204.98) v1(318.16,208.53) v1(323.16,208.53) v1(323.16,204.98) v1(328.29,204.98) v1(336.68,210.82) v1(336.68,204.98) v1(336.68,198.37) v1(350.56,210.82) v1(350.65,204.85) v1(350.65,198.75) v1(378.47,255.02) v1(378.47,252.73) v1(378.47,250.44) v1(378.47,248.16) v1(378.47,245.87) v1(378.47,241.3) v1(378.47,239.01) v1(378.47,236.73) v1(378.47,234.44) v1(378.47,232.16) v1(378.47,229.87) v1(378.47,227.58) v1(378.47,225.3) v1(378.47,223.01) v1(378.47,220.73)
S1_OSC4_N:
  vias: v1(353.24,240.1) v1(354.83,239.85)
S1_OSC4_P:
  vias: v1(353.24,238.83) v1(354.83,238.87)
S1_OSC4_R_N:
  vias: v1(352.24,241.37) v1(352.24,240.1)
S1_OSC4_R_P:
  vias: v1(352.24,238.83) v1(352.24,237.56)
S1_OSC5_6_GND: length 4.5
  BOTTOM w0.305: C473.2 v1(54.48,202.74) ; C472.2 v1(54.48,219.88)
  BOTTOM w0.508: v1(59.44,199.57) 58.94,199.07 OSC6.3 ; OSC5.3 58.94,216.22 v1(59.44,216.71)
  vias: v1(51.68,223.31) v1(51.68,210.1) v1(54.49,220.9) v1(54.49,203.75) v1(70.99,211.33) v2(42.99,217.79) v2(42.99,215.63) v2(42.99,200.64) v2(42.99,198.48) v2(43.82,220.2) v2(43.82,213.21) v2(43.82,203.06) v2(43.82,196.07) v2(45.97,217.79) v2(45.97,215.63) v2(45.97,200.64) v2(45.97,198.48) v2(46.35,221.02) v2(46.35,212.39) v2(46.35,203.88) v2(46.35,195.24) v2(46.74,217.79) v2(46.74,215.63) v2(46.74,200.64) v2(46.74,198.48) v2(48.89,220.2) v2(48.89,213.21) v2(48.89,203.06) v2(48.89,196.07) v2(49.72,217.79) v2(49.72,215.63) v2(49.72,200.64) v2(49.72,198.48)
S1_OSC5_A_N: length 2.9
  BOTTOM w0.109: K15.3 R268.1
S1_OSC5_A_P: length 2.9
  BOTTOM w0.109: K15.7 R267.1
S1_OSC5_B_N: length 12
  TOP w0.109: v1(49.4,223.31) 50.55,222.16 50.55,217.47 51.07,216.94 53,216.94 53.22,217.16 v1(53.22,218.61)
  BOTTOM w0.109: R256.1 v1(53.22,218.61)
S1_OSC5_B_P: length 12
  TOP w0.109: v1(49.4,210.1) 50.55,211.25 50.55,215.94 51.07,216.47 53,216.47 53.22,216.25 v1(53.22,214.8)
  BOTTOM w0.109: R255.1 v1(53.22,214.8)
S1_OSC5_C_N: length 2.3
  BOTTOM w0.109: R256.2 54.62,216.94 55.38,216.94 55.63,217.19 OSC5.5
S1_OSC5_C_P: length 2.3
  BOTTOM w0.109: R255.2 54.62,216.47 55.38,216.47 55.63,216.22 OSC5.4
S1_OSC5_N: length 2.3
  BOTTOM w0.117: K15.2 v1(44.42,222.68)
S1_OSC5_P: length 2.3
  BOTTOM w0.117: K15.8 v1(44.42,210.74)
S1_OSC6_A_N: length 2.9
  BOTTOM w0.109: K16.3 R269.1
S1_OSC6_A_P: length 2.9
  BOTTOM w0.109: K16.7 R270.1
S1_OSC6_B_N: length 12
  TOP w0.109: v1(53.22,201.47) 53.22,200.02 53,199.8 51.07,199.8 50.55,200.32 50.55,205.02 v1(49.4,206.17)
  BOTTOM w0.109: R258.1 v1(53.22,201.47)
S1_OSC6_B_P: length 12
  TOP w0.109: v1(49.4,192.96) 50.55,194.11 50.55,198.8 51.07,199.33 53,199.33 53.22,199.11 v1(53.22,197.66)
  BOTTOM w0.109: R257.1 v1(53.22,197.66)
S1_OSC6_C_N: length 2.3
  BOTTOM w0.109: R258.2 54.62,199.8 55.38,199.8 55.63,200.05 OSC6.5
S1_OSC6_C_P: length 2.3
  BOTTOM w0.109: OSC6.4 55.63,199.07 55.38,199.33 54.62,199.33 R257.2
S1_OSC6_N: length 2.3
  BOTTOM w0.117: K16.2 v1(44.42,205.53)
S1_OSC6_P: length 2.3
  BOTTOM w0.117: K16.8 v1(44.42,193.59)
S1_OSC7_8_GND: length 4.5
  BOTTOM w0.305: C477.2 v1(54.48,179.07) ; C475.2 v1(54.48,161.93)
  BOTTOM w0.508: OSC7.3 58.94,158.26 v1(59.44,158.76) ; v1(59.44,175.9) 58.94,175.41 OSC8.3
  vias: v1(54.49,180.09) v1(54.49,162.94) v2(42.99,176.97) v2(42.99,174.82) v2(42.99,159.83) v2(42.99,157.67) v2(43.82,179.39) v2(43.82,172.4) v2(43.82,162.24) v2(43.82,155.26) v2(45.97,176.97) v2(45.97,174.82) v2(45.97,159.83) v2(45.97,157.67) v2(46.35,180.21) v2(46.35,171.58) v2(46.35,163.07) v2(46.35,154.43) v2(46.74,176.97) v2(46.74,174.82) v2(46.74,159.83) v2(46.74,157.67) v2(48.89,179.39) v2(48.89,172.4) v2(48.89,162.24) v2(48.89,155.26) v2(49.72,176.97) v2(49.72,174.82) v2(49.72,159.83) v2(49.72,157.67)
S1_OSC7_A_N: length 2.9
  BOTTOM w0.109: K18.3 R277.1
S1_OSC7_A_P: length 2.9
  BOTTOM w0.109: K18.7 R278.1
S1_OSC7_B_N: length 12
  TOP w0.109: v1(49.4,165.35) 50.55,164.2 50.55,159.51 51.07,158.99 53,158.99 53.22,159.2 v1(53.22,160.66)
  BOTTOM w0.109: R272.1 v1(53.22,160.66)
S1_OSC7_B_P: length 12
  TOP w0.109: v1(49.4,152.15) 50.55,153.3 50.55,157.99 51.07,158.51 53,158.51 53.22,158.3 v1(53.22,156.84)
  BOTTOM w0.109: R271.1 v1(53.22,156.84)
S1_OSC7_C_N: length 2.3
  BOTTOM w0.109: OSC7.5 55.63,159.24 55.38,158.99 54.62,158.99 R272.2
S1_OSC7_C_P: length 2.3
  BOTTOM w0.109: OSC7.4 55.63,158.26 55.38,158.51 54.62,158.51 R271.2
S1_OSC7_N: length 2.3
  BOTTOM w0.117: K18.2 v1(44.42,164.72)
S1_OSC7_P: length 2.3
  BOTTOM w0.117: K18.8 v1(44.42,152.78)
S1_OSC8_A_N: length 2.9
  BOTTOM w0.109: K20.3 R285.1
S1_OSC8_A_P: length 2.9
  BOTTOM w0.109: K20.7 R286.1
S1_OSC8_B_N: length 12
  TOP w0.109: v1(49.4,182.5) 50.55,181.35 50.55,176.66 51.07,176.13 53,176.13 53.22,176.35 v1(53.22,177.8)
  BOTTOM w0.109: R279.1 v1(53.22,177.8)
S1_OSC8_B_P: length 12
  TOP w0.109: v1(49.4,169.29) 50.55,170.44 50.55,175.13 51.07,175.66 53,175.66 53.22,175.44 v1(53.22,173.99)
  BOTTOM w0.109: R280.1 v1(53.22,173.99)
S1_OSC8_C_N: length 2.3
  BOTTOM w0.109: R279.2 54.62,176.13 55.38,176.13 55.63,176.38 OSC8.5
S1_OSC8_C_P: length 2.3
  BOTTOM w0.109: R280.2 54.62,175.66 55.38,175.66 55.63,175.41 OSC8.4
S1_OSC8_N: length 2.3
  BOTTOM w0.117: K20.2 v1(44.42,181.86)
S1_OSC8_P: length 2.3
  BOTTOM w0.117: K20.8 v1(44.42,169.93)
S1_PCIE_RX_N[0]: length 124.5
  L07_DIG w0.079: 296.83,227.71 296.83,227.73 296.82,227.74 296.82,233.15 319.75,256.09 356.83,256.09 359.54,258.8 359.54,270.61 356.41,273.74 338.58,273.74 338,274.32 338,276.2 338.92,277.11 342.72,277.11 342.9,276.94 342.9,276.63 342.74,276.48 v3(342.05,276.48)
  L07_DIG w0.102: v1(296.83,227.03) 296.83,227.71
  BOTTOM w0.117: C252.1 R117.1 arc(342.5,276.84) 342.24,276.67 v3(342.05,276.48)
S1_PCIE_RX_N[1]: length 124.5
  L07_DIG w0.079: v3(326.81,276.48) 327.51,276.48 327.65,276.62 327.65,276.94 327.48,277.11 323.9,277.11 322.49,275.7 322.49,271.09 324.73,268.85 348.23,268.85 350.09,267 350.09,259.9 348.03,257.84 315.32,257.84 302.75,245.27 302.75,241.6 295.22,234.08 295.22,227.74 295.23,227.73 295.23,227.71
  L07_DIG w0.102: v1(295.23,227.03) 295.23,227.71
  BOTTOM w0.117: C256.1 R125.1 arc(327.26,276.84) 327,276.67 v3(326.81,276.48)
S1_PCIE_RX_N[2]: length 124.5
  L07_DIG w0.079: v3(311.57,278.13) 311.57,277.51 311.34,277.29 310.02,277.29 307.45,274.72 307.45,266.15 309.59,264.02 341.76,264.02 342.3,263.47 342.3,262 341.7,261.41 314.75,261.41 298.23,244.89 298.23,240.55 293.64,235.96 293.64,227.74 293.63,227.73 293.63,227.71
  L07_DIG w0.102: 293.63,227.71 v1(293.63,227.03)
  BOTTOM w0.117: v3(311.57,278.13) 311.76,277.94 arc(312.02,277.76) R129.1 C261.1
S1_PCIE_RX_N[3]: length 124.5
  L07_DIG w0.079: v3(296.33,278.13) 296.33,277.53 296.08,277.28 293.94,277.28 289.33,272.67 289.33,270.97 287.46,269.1 277.07,269.1 270.83,262.87 253.84,262.87 251.98,261.01 251.98,257.68 253.43,256.24 286.61,256.24 289.33,253.52 289.33,241.46 292.04,238.74 292.04,227.74 292.03,227.73 292.03,227.71
  L07_DIG w0.102: 292.03,227.71 v1(292.03,227.03)
  BOTTOM w0.117: C265.1 R133.1 arc(296.78,277.76) 296.52,277.94 v3(296.33,278.13)
S1_PCIE_RX_N[4]: length 124.5
  L07_DIG w0.079: 290.43,227.71 290.43,227.73 290.44,227.74 290.44,237.03 287.33,240.13 287.33,251.55 285.43,253.46 245.44,253.46 244.09,254.81 244.09,261.84 246.6,264.35 257.01,264.35 262.41,269.75 262.41,271.9 264.66,274.15 276.29,274.15 279.43,277.29 280.87,277.29 281.09,277.51 v3(281.09,278.13)
  L07_DIG w0.102: 290.43,227.71 v1(290.43,227.03)
  BOTTOM w0.117: v3(281.09,278.13) 281.28,277.94 arc(281.54,277.76) R137.1 C269.1
S1_PCIE_RX_N[5]: length 124.5
  L07_DIG w0.079: v3(265.85,278.13) 265.85,277.54 265.58,277.27 264.4,277.27 256.25,269.12 232.81,269.12 231.17,267.48 231.17,265.13 244.92,251.38 275.67,251.38 276.87,250.18 276.87,243.37 280.71,239.53 282.43,239.53 288.84,233.12 288.84,227.74 288.83,227.73 288.83,227.71
  L07_DIG w0.102: 288.83,227.71 v1(288.83,227.03)
  BOTTOM w0.117: v3(265.85,278.13) 266.04,277.94 arc(266.3,277.76) R142.1 C273.1
S1_PCIE_RX_N[6]: length 124.5
  L07_DIG w0.079: 287.23,227.71 287.23,227.73 287.24,227.74 287.24,230.58 270.33,247.49 227.57,247.49 225.77,249.3 225.77,271.38 228.45,274.06 246.15,274.06 249.35,277.25 250.25,277.25 250.61,277.61 v3(250.61,278.13)
  L07_DIG w0.102: 287.23,227.71 v1(287.23,227.03)
  BOTTOM w0.117: C277.1 R146.1 arc(251.06,277.76) 250.8,277.94 v3(250.61,278.13)
S1_PCIE_RX_N[7]: length 124.5
  L07_DIG w0.079: v3(235.37,278.13) 235.37,277.63 234.98,277.24 219.76,277.24 217.44,274.92 217.44,250.48 222.18,245.74 268.46,245.74 285.64,228.56 285.64,227.72 285.63,227.71
  L07_DIG w0.102: 285.63,227.71 v1(285.63,227.03)
  BOTTOM w0.117: v3(235.37,278.13) 235.56,277.94 arc(235.82,277.76) R150.1 C281.1
S1_PCIE_RX_P[0]: length 124.5
  L07_DIG w0.079: 296.43,227.71 296.43,227.73 296.44,227.74 296.44,233.31 319.6,256.47 356.67,256.47 359.16,258.96 359.16,270.45 356.25,273.36 338.42,273.36 337.62,274.16 337.62,276.36 338.76,277.5 341.89,277.5 342.05,277.65 v3(342.05,278.13)
  L07_DIG w0.102: v1(296.83,226.23) 296.43,226.63 296.43,227.71
  BOTTOM w0.117: v3(342.05,278.13) 342.24,277.94 arc(342.5,277.76) R118.1 C253.1
S1_PCIE_RX_P[1]: length 124.5
  L07_DIG w0.079: v3(326.81,278.13) 326.81,277.65 326.65,277.5 323.74,277.5 322.11,275.86 322.11,270.93 324.57,268.47 348.07,268.47 349.7,266.84 349.7,260.06 347.87,258.23 315.16,258.23 302.36,245.43 302.36,241.76 294.84,234.23 294.84,227.74 294.83,227.73 294.83,227.71
  L07_DIG w0.102: v1(295.23,226.23) 294.83,226.63 294.83,227.71
  BOTTOM w0.117: v3(326.81,278.13) 327,277.94 arc(327.26,277.76) R126.1 C257.1
S1_PCIE_RX_P[2]: length 124.5
  L07_DIG w0.079: 294.03,227.71 294.03,227.73 294.02,227.74 294.02,235.8 298.61,240.39 298.61,244.73 314.9,261.02 341.86,261.02 342.68,261.84 342.68,263.63 341.91,264.4 309.74,264.4 307.84,266.31 307.84,274.56 310.18,276.9 311.49,276.9 311.57,276.83 v3(311.57,276.48)
  L07_DIG w0.102: 294.03,227.71 294.03,226.63 v1(293.63,226.23)
  BOTTOM w0.117: C260.1 R130.1 arc(312.02,276.84) 311.76,276.67 v3(311.57,276.48)
S1_PCIE_RX_P[3]: length 124.5
  L07_DIG w0.079: v3(296.33,276.48) 296.33,276.82 296.25,276.9 294.1,276.9 289.71,272.51 289.71,270.81 287.62,268.72 277.23,268.72 270.99,262.48 254,262.48 252.37,260.86 252.37,257.84 253.59,256.62 286.77,256.62 289.71,253.68 289.71,241.61 292.42,238.9 292.42,227.74 292.43,227.73 292.43,227.71
  L07_DIG w0.102: v1(292.03,226.23) 292.43,226.63 292.43,227.71
  BOTTOM w0.117: v3(296.33,276.48) 296.52,276.67 arc(296.78,276.84) R134.1 C264.1
S1_PCIE_RX_P[4]: length 124.5
  L07_DIG w0.079: 290.83,227.71 290.83,227.73 290.82,227.74 290.82,237.19 287.72,240.29 287.72,251.71 285.59,253.84 245.6,253.84 244.48,254.96 244.48,261.68 246.76,263.97 257.17,263.97 262.8,269.59 262.8,271.74 264.82,273.77 276.45,273.77 279.59,276.9 281.01,276.9 281.09,276.83 v3(281.09,276.48)
  L07_DIG w0.102: 290.83,227.71 290.83,226.63 v1(290.43,226.23)
  BOTTOM w0.117: v3(281.09,276.48) 281.28,276.67 arc(281.54,276.84) R138.1 C268.1
S1_PCIE_RX_P[5]: length 124.5
  L07_DIG w0.079: v3(265.85,276.48) 265.85,276.81 265.77,276.89 264.56,276.89 256.41,268.74 232.97,268.74 231.55,267.32 231.55,265.29 245.08,251.77 275.83,251.77 277.26,250.34 277.26,243.53 280.87,239.92 282.59,239.92 289.22,233.28 289.22,227.74 289.23,227.73 289.23,227.71
  L07_DIG w0.102: 289.23,227.71 289.23,226.63 v1(288.83,226.23)
  BOTTOM w0.117: v3(265.85,276.48) 266.04,276.67 arc(266.3,276.84) R141.1 C272.1
S1_PCIE_RX_P[6]: length 124.5
  L07_DIG w0.079: 287.63,227.71 287.62,227.72 287.62,230.74 270.49,247.88 227.73,247.88 226.15,249.46 226.15,271.22 228.61,273.68 246.31,273.68 249.5,276.87 250.53,276.87 250.61,276.79 v3(250.61,276.48)
  L07_DIG w0.102: 287.63,227.71 287.63,226.63 v1(287.23,226.23)
  BOTTOM w0.117: v3(250.61,276.48) 250.8,276.67 arc(251.06,276.84) R145.1 C276.1
S1_PCIE_RX_P[7]: length 124.5
  L07_DIG w0.079: 286.03,227.71 286.02,227.72 286.02,228.72 268.61,246.13 222.34,246.13 217.82,250.64 217.82,274.76 219.92,276.86 235.29,276.86 235.37,276.78 v3(235.37,276.48)
  L07_DIG w0.102: 286.03,227.71 286.03,226.63 v1(285.63,226.23)
  BOTTOM w0.117: v3(235.37,276.48) 235.56,276.67 arc(235.82,276.84) R149.1 C280.1
S1_PCIE_TX_1_N[0]: length 7.4
  BOTTOM w0.117: S1_PCIE_TX_N[0].1 C254.1
S1_PCIE_TX_1_N[1]: length 7.4
  BOTTOM w0.117: S1_PCIE_TX_N[1].1 C258.1
S1_PCIE_TX_1_N[2]: length 7.4
  BOTTOM w0.117: S1_PCIE_TX_N[2].1 C262.1
S1_PCIE_TX_1_N[3]: length 7.4
  BOTTOM w0.117: S1_PCIE_TX_N[3].1 C266.1
S1_PCIE_TX_1_N[4]: length 7.4
  BOTTOM w0.117: S1_PCIE_TX_N[4].1 C270.1
S1_PCIE_TX_1_N[5]: length 7.4
  BOTTOM w0.117: S1_PCIE_TX_N[5].1 C274.1
S1_PCIE_TX_1_N[6]: length 7.4
  BOTTOM w0.117: S1_PCIE_TX_N[6].1 C278.1
S1_PCIE_TX_1_N[7]: length 7.4
  BOTTOM w0.117: S1_PCIE_TX_N[7].1 C282.1
S1_PCIE_TX_1_P[0]: length 7.4
  BOTTOM w0.117: S1_PCIE_TX_P[0].1 C255.1
S1_PCIE_TX_1_P[1]: length 7.4
  BOTTOM w0.117: S1_PCIE_TX_P[1].1 C259.1
S1_PCIE_TX_1_P[2]: length 7.4
  BOTTOM w0.117: S1_PCIE_TX_P[2].1 C263.1
S1_PCIE_TX_1_P[3]: length 7.4
  BOTTOM w0.117: S1_PCIE_TX_P[3].1 C267.1
S1_PCIE_TX_1_P[4]: length 7.4
  BOTTOM w0.117: S1_PCIE_TX_P[4].1 C271.1
S1_PCIE_TX_1_P[5]: length 7.4
  BOTTOM w0.117: S1_PCIE_TX_P[5].1 C275.1
S1_PCIE_TX_1_P[6]: length 7.4
  BOTTOM w0.117: S1_PCIE_TX_P[6].1 C279.1
S1_PCIE_TX_1_P[7]: length 7.4
  BOTTOM w0.117: S1_PCIE_TX_P[7].1 C283.1
S1_PCIE_TX_N[0]: length 124.5
  L09_DIG w0.079: 295.63,227.71 295.63,227.73 295.84,227.94 295.84,231.8 320.19,256.15 361.48,256.15 364.34,259.01 364.34,271.78 359.01,277.11 345.07,277.11 344.94,276.98 344.94,276.62 345.08,276.48 v3(345.69,276.48)
  L09_DIG w0.102: v1(296.03,224.63) 295.63,225.03 295.63,227.71
  BOTTOM w0.117: C254.2 R123.1 arc(345.24,276.84) 345.5,276.67 v3(345.69,276.48)
S1_PCIE_TX_N[1]: length 124.5
  L09_DIG w0.079: v3(330.45,276.48) 329.9,276.48 329.71,276.67 329.71,276.98 329.9,277.16 337.9,277.16 340.82,274.24 354.01,274.24 355.92,272.33 355.92,259.95 353.58,257.62 319.63,257.62 294.24,232.22 294.24,227.94 294.03,227.73 294.03,227.71
  L09_DIG w0.102: 294.03,227.71 294.03,225.03 v1(294.43,224.63)
  BOTTOM w0.117: v3(330.45,276.48) 330.26,276.67 arc(330,276.84) R127.1 C256.2
S1_PCIE_TX_N[2]: length 124.5
  L09_DIG w0.079: v3(315.21,278.13) 315.21,277.65 315.52,277.35 317.19,277.35 318.18,278.34 318.18,282.07 319.6,283.49 322.18,283.49 323.91,281.76 323.91,276.79 326.47,274.22 335.54,274.22 340.67,269.1 343.09,269.1 344.68,267.51 344.68,260.99 342.43,258.75 318.63,258.75 293.02,233.14 293.02,227.94 293.23,227.73 293.23,227.71
  L09_DIG w0.102: v1(292.83,224.63) 293.23,225.03 293.23,227.71
  BOTTOM w0.117: C261.2 R131.1 arc(314.76,277.76) 315.02,277.94 v3(315.21,278.13)
S1_PCIE_TX_N[3]: length 124.5
  L09_DIG w0.079: 291.63,227.71 291.63,227.73 291.42,227.94 291.42,234.43 305.38,248.39 305.38,251.98 303.69,253.67 283,253.67 282.43,254.24 282.43,256.04 283.14,256.75 313.07,256.75 314.27,257.96 314.27,271.89 311.44,274.73 309.85,274.73 307.24,277.34 300.28,277.34 299.97,277.65 v3(299.97,278.13)
  L09_DIG w0.102: v1(291.23,224.63) 291.63,225.03 291.63,227.71
  BOTTOM w0.117: C266.2 R135.1 arc(299.52,277.76) 299.78,277.94 v3(299.97,278.13)
S1_PCIE_TX_N[4]: length 124.5
  L09_DIG w0.079: 290.03,227.71 290.03,227.73 289.82,227.94 289.82,250.61 288.65,251.78 254.47,251.78 253.6,252.65 253.6,255.68 254.55,256.63 279.27,256.63 289.82,267.18 289.82,276.69 289.16,277.35 285.04,277.35 284.73,277.65 v3(284.73,278.13)
  L09_DIG w0.102: v1(289.63,224.63) 290.03,225.03 290.03,227.71
  BOTTOM w0.117: v3(284.73,278.13) 284.54,277.94 arc(284.28,277.76) R139.1 C270.2
S1_PCIE_TX_N[5]: length 124.5
  L09_DIG w0.079: 288.43,227.71 288.43,227.73 288.22,227.94 288.22,229.93 283.92,234.23 283.92,236.97 277.47,243.42 277.47,245.59 275.58,247.49 243.91,247.49 242.57,248.83 242.57,256.77 244.18,258.38 270.7,258.38 273.71,261.39 273.71,275.85 272.22,277.34 269.81,277.34 269.49,277.65 v3(269.49,278.13)
  L09_DIG w0.102: 288.43,227.71 288.43,225.03 v1(288.03,224.63)
  BOTTOM w0.117: v3(269.49,278.13) 269.3,277.94 arc(269.04,277.76) R143.1 C274.2
S1_PCIE_TX_N[6]: length 124.5
  L09_DIG w0.079: 286.83,227.71 286.83,227.73 286.62,227.94 286.62,229.46 281.83,234.25 281.83,236.02 273.48,244.37 236.97,244.37 231.61,249.74 231.61,257.86 235.92,262.16 255.4,262.16 258.27,265.04 258.27,274.92 255.84,277.35 254.56,277.35 254.25,277.65 v3(254.25,278.13)
  L09_DIG w0.102: v1(286.43,224.63) 286.83,225.03 286.83,227.71
  BOTTOM w0.117: C278.2 R147.1 arc(253.8,277.76) 254.06,277.94 v3(254.25,278.13)
S1_PCIE_TX_N[7]: length 124.5
  L09_DIG w0.079: 285.23,227.71 285.23,227.73 285.02,227.94 285.02,228.65 271,242.68 226.51,242.68 225.83,243.36 225.83,261.36 228.11,263.64 242.06,263.64 243.59,265.18 243.59,274.86 241.1,277.35 239.32,277.35 239.01,277.65 v3(239.01,278.13)
  L09_DIG w0.102: 285.23,227.71 285.23,225.03 v1(284.83,224.63)
  BOTTOM w0.117: C281.2 R151.1 arc(238.56,277.76) 238.82,277.94 v3(239.01,278.13)
S1_PCIE_TX_P[0]: length 124.5
  L09_DIG w0.079: v3(345.69,278.13) 345.69,277.65 345.85,277.5 359.17,277.5 364.73,271.94 364.73,258.85 361.64,255.77 320.35,255.77 296.22,231.64 296.22,227.94 296.43,227.73 296.43,227.71
  L09_DIG w0.102: v1(296.03,223.83) 296.43,224.23 296.43,227.71
  BOTTOM w0.117: v3(345.69,278.13) 345.5,277.94 arc(345.24,277.76) R124.1 C253.2
